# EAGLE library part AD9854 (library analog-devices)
CMOS 300 MSPS Quadrature Complete DDS Source: http://www.analog.com/static/imported-files/data_sheets/AD9854.pdf
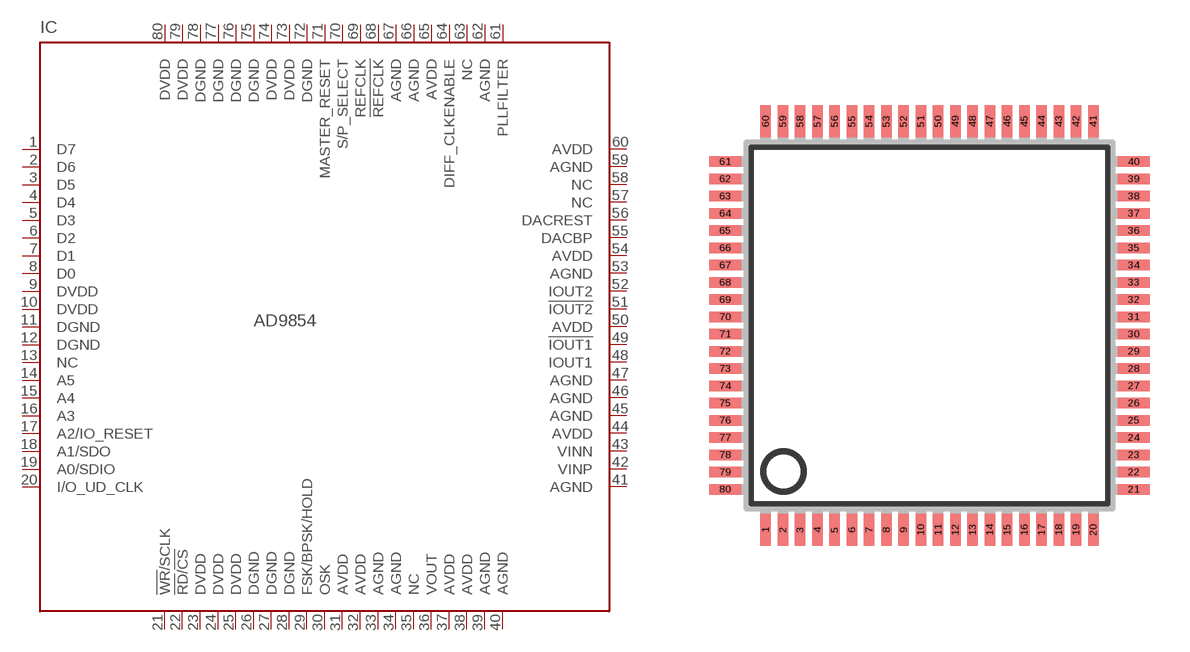
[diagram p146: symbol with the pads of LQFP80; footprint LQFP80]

Designator prefix IC

## AD9854 (MPN: AD9854ASTZ; OC_FARNELL: unknown; OC_NEWARK: 15P1074)  [LQFP80]
1  D7  hiz
2  D6  hiz
3  D5  hiz
4  D4  hiz
5  D3  hiz
6  D2  hiz
7  D1  hiz
8  D0  hiz
9  DVDD  pwr
10  DVDD  pwr
11  DGND  pwr
12  DGND  pwr
13  NC  nc
14  A5  in
15  A4  in
16  A3  in
17  A2/IO_RESET  in
18  A1/SDO  in
19  A0/SDIO  in
20  I/O_UD_CLK  in
21  !WR!/SCLK  in
22  !RD!/!CS!  in
23  DVDD  pwr
24  DVDD  pwr
25  DVDD  pwr
26  DGND  pwr
27  DGND  pwr
28  DGND  pwr
29  FSK/BPSK/HOLD  in
30  OSK  in
31  AVDD  pwr
32  AVDD  pwr
33  AGND  pwr
34  AGND  pwr
35  NC  nc
36  VOUT  out
37  AVDD  pwr
38  AVDD  pwr
39  AGND  pwr
40  AGND  pwr
41  AGND  pwr
42  VINP  in
43  VINN  in
44  AVDD  pwr
45  AGND  pwr
46  AGND  pwr
47  AGND  pwr
48  IOUT1  out
49  !IOUT1  out
50  AVDD  pwr
51  !IOUT2  out
52  IOUT2  out
53  AGND  pwr
54  AVDD  pwr
55  DACBP  in
56  DACREST  in
57  NC  nc
58  NC  nc
59  AGND  pwr
60  AVDD  pwr
61  PLLFILTER  in
62  AGND  pwr
63  NC  nc
64  DIFF_CLKENABLE  in
65  AVDD  pwr
66  AGND  pwr
67  AGND  pwr
68  !REFCLK  in
69  REFCLK  in
70  S/P_SELECT  in
71  MASTER_RESET  in
72  DGND  pwr
73  DVDD  pwr
74  DVDD  pwr
75  DGND  pwr
76  DGND  pwr
77  DGND  pwr
78  DGND  pwr
79  DVDD  pwr
80  DVDD  pwr

## Footprint LQFP80 (pad centres in mm)
80 Lead LQFP_ED (SQ-80) (ST-80) Source: www.analog.com .. AD9852_b.pdf
smd 0.4 x 1.2: 1 -6.175,-7.7; 2 -5.525,-7.7; 3 -4.875,-7.7; 4 -4.225,-7.7; 5 -3.575,-7.7; 6 -2.925,-7.7; 7 -2.275,-7.7; 8 -1.625,-7.7; 9 -0.975,-7.7; 10 -0.325,-7.7; 11 0.325,-7.7; 12 0.975,-7.7; 13 1.625,-7.7; 14 2.275,-7.7; 15 2.925,-7.7; 16 3.575,-7.7; 17 4.225,-7.7; 18 4.875,-7.7; 19 5.525,-7.7; 20 6.175,-7.7; 41 6.175,7.7; 42 5.525,7.7; 43 4.875,7.7; 44 4.225,7.7; 45 3.575,7.7; 46 2.925,7.7; 47 2.275,7.7; 48 1.625,7.7; 49 0.975,7.7; 50 0.325,7.7; 51 -0.325,7.7; 52 -0.975,7.7; 53 -1.625,7.7; 54 -2.275,7.7; 55 -2.925,7.7; 56 -3.575,7.7; 57 -4.225,7.7; 58 -4.875,7.7; 59 -5.525,7.7; 60 -6.175,7.7
smd 1.2 x 0.4: 21 7.7,-6.175; 22 7.7,-5.525; 23 7.7,-4.875; 24 7.7,-4.225; 25 7.7,-3.575; 26 7.7,-2.925; 27 7.7,-2.275; 28 7.7,-1.625; 29 7.7,-0.975; 30 7.7,-0.325; 31 7.7,0.325; 32 7.7,0.975; 33 7.7,1.625; 34 7.7,2.275; 35 7.7,2.925; 36 7.7,3.575; 37 7.7,4.225; 38 7.7,4.875; 39 7.7,5.525; 40 7.7,6.175; 61 -7.7,6.175; 62 -7.7,5.525; 63 -7.7,4.875; 64 -7.7,4.225; 65 -7.7,3.575; 66 -7.7,2.925; 67 -7.7,2.275; 68 -7.7,1.625; 69 -7.7,0.975; 70 -7.7,0.325; 71 -7.7,-0.325; 72 -7.7,-0.975; 73 -7.7,-1.625; 74 -7.7,-2.275; 75 -7.7,-2.925; 76 -7.7,-3.575; 77 -7.7,-4.225; 78 -7.7,-4.875; 79 -7.7,-5.525; 80 -7.7,-6.175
